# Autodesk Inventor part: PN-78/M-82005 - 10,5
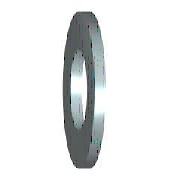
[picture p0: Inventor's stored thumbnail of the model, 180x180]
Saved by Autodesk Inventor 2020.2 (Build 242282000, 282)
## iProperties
Manager: www.cadconsulting.pl
Company: Fabian Stasiak CAD Consulting
Created: 2006-02
Part Number: PN-78/M-82005 - 10,5
Material: Stal, miękka
Description: Podkładki okrągłe, szereg nieobrobiony
Document SubType Name: Modeling
Standard: PN-78/M-82005
Designer: F.Stasiak
Standards Organization: PN
Language: pl-PL
Size Designation: 10,5
Categories: <MemberInstance><Categories><Category DisplayName="Mocowania" InternalName="e4da775c-781d-43d5-af7c-5136215cf5a6" Mnemonic="FSTN"><Category DisplayName="Podkład
Density: 1 g/cm^3
Appearance: Stal
Author: F.Stasiak
Subject: Zbiór ćwiczeń. Autodesk Inventor 2020. Kurs podstawowy
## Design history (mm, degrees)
sketch "Szkic"
  geometry: C1 r 10.5 at (0, 0); C2 r 5.25 at (0, 0); 1 further point
  constraints: 2 centre point, 2 coincident
  dimensions: "d0" = 10.5 diameter of C2 (= SD1); "d1" = 21 diameter of C1 (= SD2)
extrude "Bryła" new body sketch "Szkic" distance "d2" = 2 (= SD); taper "d3" = 0 deg
workaxis "Work Axis1"
workplane "Work Plane1"
node "Bryła1"
node "Korpusy bryłowe"
node "Korpusy powierzchniowe"
other parameters: "SD1" = 10.5 [user parameter; used in 1 equation term], "SD2" = 21 [user parameter; used in 1 equation term], "SD" = 2 [user parameter; used in 1 equation term], "d4" = 0, "d5" = 0, "d6" = 0, "d7" = 0
